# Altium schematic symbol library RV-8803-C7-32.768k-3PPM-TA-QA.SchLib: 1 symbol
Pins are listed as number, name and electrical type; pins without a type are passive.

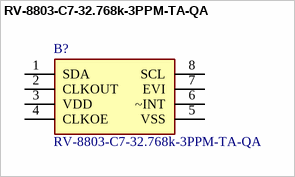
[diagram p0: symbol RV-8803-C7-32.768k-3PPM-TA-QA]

## RV-8803-C7-32.768k-3PPM-TA-QA
designator B?
RV-8803-C7 8-Terminal Ceramic Leadless Chip Carrier [LCC8]; Manufacturer_Name: Micro Crystal AG; Geometry.Height: 0.8mm
footprint RV8803C7
pins: 1 SDA, 2 CLKOUT, 3 VDD, 4 CLKOE, 5 VSS, 6 ~INT, 7 EVI, 8 SCL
